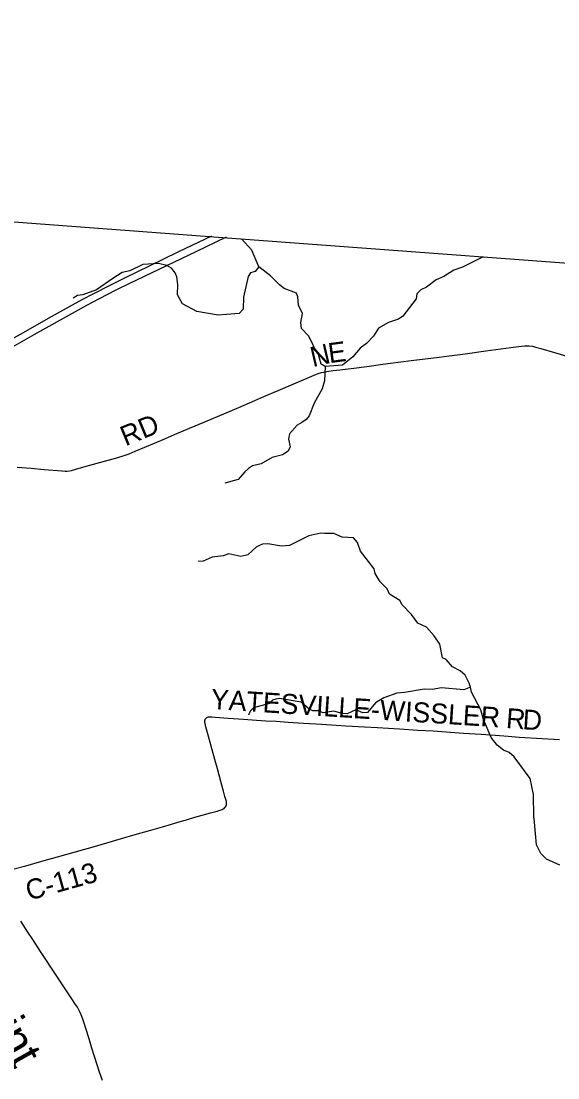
# Model space of a CAD drawing. Extents: x -51392 to 1635000, y 156707 to 696232.
# Drawn here: x 136510 to 144570, y 535301 to 551154 of the extents above; entities that cross this region are included whole.
import ezdxf

# ---------------------------------------------------------------- set-up
doc = ezdxf.new("R2010")
doc.units = 0
for name, color, linetype in [('GM_X_Adjacent_County', 7, 'Continuous'), ('GM_X_County', 7, 'Continuous'), ('GM_X_County_Road', 7, 'Continuous'), ('GM_X_County_Road_Text', 7, 'Continuous'), ('GM_X_Interstate_Route', 7, 'Continuous'), ('GM_X_Minor_River', 7, 'Continuous'), ('GM_X_Minor_River_Text', 7, 'Continuous'), ('GM_X_State_Route', 7, 'Continuous'), ('GM_X_Township', 7, 'Continuous'), ('GM_X_Township_Road', 7, 'Continuous'), ('GM_X_Township_Road_Text', 7, 'Continuous')]:
    doc.layers.add(name, color=color, linetype=linetype)

msp = doc.modelspace()

# ---------------------------------------------------------------- linework, layer by layer
at = {"layer": 'GM_X_Adjacent_County'}
msp.add_lwpolyline([(96623, 551154), (109974, 550151), (113344, 549888), (113818, 549851), (117011, 549602), (121021, 549289), (121855, 549224), (127787, 548783), (132864, 548406), (139538, 547909), (147829, 547293), (153416, 546885), (154887, 546778), (157022, 546663), (159649, 546538), (163080, 546381), (166694, 546239), (167692, 546175), (177006, 545575)], dxfattribs=at)
at = {"layer": 'GM_X_County'}
msp.add_lwpolyline([(96623, 551154), (109974, 550151), (113344, 549888), (113818, 549851), (117011, 549602), (121021, 549289), (121855, 549224), (127787, 548783), (132864, 548406), (139538, 547909), (147829, 547293), (153416, 546885), (154887, 546778), (157022, 546663), (159649, 546538), (163080, 546381), (166694, 546239), (167692, 546175), (177006, 545575)], dxfattribs=at)
at = {"layer": 'GM_X_County_Road'}
msp.add_lwpolyline([(136386, 538430), (136583, 538483), (136819, 538550), (137056, 538617), (137184, 538653), (137309, 538687), (137466, 538731), (137577, 538762), (138018, 538890), (138223, 538950), (138459, 539019), (138632, 539068), (138768, 539108), (138900, 539146), (138994, 539174), (139119, 539212), (139230, 539243), (139353, 539276), (139452, 539303), (139499, 539316), (139530, 539328), (139544, 539335), (139558, 539344), (139571, 539355), (139581, 539367), (139589, 539381), (139593, 539396), (139596, 539412), (139595, 539429), (139593, 539445), (139586, 539477), (139570, 539524), (139548, 539603), (139540, 539635), (139509, 539746), (139457, 539935), (139419, 540078), (139380, 540220), (139320, 540442), (139284, 540568), (139272, 540616), (139269, 540633), (139268, 540649), (139270, 540665), (139272, 540673), (139276, 540682), (139283, 540693), (139288, 540699), (139297, 540705), (139309, 540710), (139326, 540715), (139342, 540717), (139375, 540716), (139424, 540712), (139621, 540697), (139850, 540682), (140046, 540668), (140185, 540659), (140340, 540650), (140520, 540638), (140749, 540624), (141028, 540605), (141240, 540592), (141388, 540584), (141666, 540569), (141862, 540558), (142190, 540537), (142468, 540519), (142697, 540505), (142893, 540493), (143155, 540474), (143416, 540455), (143629, 540440), (143825, 540425), (143989, 540413), (144332, 540392), (144594, 540377)], dxfattribs=at)
at = {"layer": 'GM_X_Interstate_Route'}
for points in [[(136250, 546320), (136580, 546504), (136922, 546697), (137238, 546874), (137427, 546976), (137602, 547068), (137847, 547194), (138068, 547303), (138643, 547581), (138880, 547696), (139373, 547934)], [(136707, 546451), (137326, 546800), (137498, 546895), (137687, 546994), (137936, 547121), (138142, 547222), (139138, 547699), (139592, 547918)], [(134408, 545154), (134597, 545261), (135640, 545849), (135736, 545905), (136140, 546131), (136707, 546451)]]:
    msp.add_lwpolyline(points, dxfattribs=at)
at = {"layer": 'GM_X_Minor_River'}
for points in [[(143446, 547620), (143138, 547462), (143009, 547417), (142858, 547322), (142742, 547273), (142598, 547161), (142514, 547124), (142453, 547062), (142441, 546990), (142244, 546729), (142176, 546685), (142027, 546634), (141878, 546549), (141803, 546426), (141696, 546320), (141599, 546247), (141491, 546117), (141336, 545992), (141075, 545972), (141015, 546010), (140964, 546187), (140917, 546246), (140883, 546326), (140828, 546435), (140718, 546544), (140711, 546634), (140734, 546766), (140675, 546895), (140666, 547017), (140644, 547071), (140458, 547143), (140388, 547200), (140253, 547333), (140081, 547468), (139977, 547720), (139822, 547889)], [(140081, 547468), (140025, 547399), (139956, 547377), (139918, 547323), (139851, 547011), (139844, 546831), (139783, 546769), (139593, 546754), (139470, 546743), (139150, 546798), (138934, 546914), (138861, 547046), (138864, 547201), (138847, 547319), (138825, 547377), (138767, 547450), (138698, 547490), (138575, 547517), (138339, 547503), (138143, 547410), (138029, 547383), (137888, 547292), (137640, 547125), (137435, 547047), (137356, 547037), (137290, 547000)], [(141075, 545972), (141068, 545756), (141029, 545640), (140913, 545422), (140835, 545232), (140791, 545176), (140726, 545131), (140656, 545091), (140542, 544964), (140524, 544882), (140551, 544767), (140522, 544701), (140436, 544650), (140279, 544607), (140114, 544512), (139983, 544485), (139925, 544443), (139868, 544391), (139771, 544278), (139568, 544225)], [(142599, 542060), (142469, 542123), (142374, 542250), (142234, 542396), (142195, 542462), (142043, 542555), (142005, 542636), (141904, 542741), (141874, 542793), (141826, 542866), (141813, 542938), (141608, 543200), (141559, 543331), (141500, 543403), (141329, 543413), (141207, 543468), (141065, 543469), (141009, 543471), (140830, 543430), (140540, 543288), (140421, 543275), (140217, 543314), (140137, 543307), (140046, 543268), (139980, 543206), (139917, 543146), (139811, 543121), (139630, 543162), (139542, 543131), (139381, 543114), (139246, 543053), (139170, 543049)], [(144598, 538490), (144400, 538583), (144313, 538668), (144251, 538799), (144220, 539136), (144210, 539220), (144203, 539551), (144155, 539792), (143912, 540116), (143838, 540181), (143756, 540216), (143657, 540293), (143569, 540408), (143453, 540679), (143414, 540822), (143272, 541089), (143256, 541164), (143240, 541224), (143177, 541342), (143105, 541409), (142986, 541466), (142894, 541577), (142840, 541602), (142797, 541806), (142714, 541931), (142599, 542060)], [(143256, 541164), (143157, 541122), (142823, 541153), (142684, 541128), (142560, 541130), (142267, 541081), (142152, 541071), (141959, 541001), (141832, 540925), (141711, 540780), (141643, 540778), (141535, 540821), (141406, 540764), (141330, 540765), (141206, 540804), (141045, 540779), (140973, 540807), (140893, 540806), (140837, 540832), (140713, 540935), (140391, 540992), (140336, 540984), (140286, 540969), (140240, 540915), (140002, 540854), (139948, 540801), (139927, 540741)]]:
    msp.add_lwpolyline(points, dxfattribs=at)
at = {"layer": 'GM_X_State_Route'}
msp.add_lwpolyline([(137732, 535262), (137689, 535386), (137614, 535620), (137569, 535761), (137525, 535902), (137487, 536028), (137459, 536120), (137438, 536183), (137413, 536246), (137386, 536303), (137355, 536361), (137318, 536418), (137270, 536486), (137171, 536637), (137036, 536842), (136801, 537199), (136684, 537377), (136613, 537487), (136507, 537653)], dxfattribs=at)
at = {"layer": 'GM_X_Township'}
msp.add_lwpolyline([(121855, 549224), (127787, 548783), (132864, 548406), (139538, 547909), (147829, 547293)], dxfattribs=at)
at = {"layer": 'GM_X_Township_Road'}
msp.add_lwpolyline([(136451, 544465), (136663, 544447), (136859, 544429), (137121, 544407), (137170, 544404), (137203, 544404), (137235, 544408), (137267, 544414), (137331, 544431), (137488, 544476), (137709, 544539), (137946, 544605), (138056, 544638), (138133, 544665), (138225, 544702), (138512, 544823), (138678, 544892), (138813, 544951), (139040, 545047), (139267, 545143), (139780, 545360), (140021, 545463), (140157, 545521), (140368, 545611), (140639, 545727), (140911, 545843), (140972, 545867), (141019, 545883), (141050, 545890), (141099, 545899), (141196, 545911), (141294, 545923), (141505, 545950), (141701, 545975), (141944, 546008), (142058, 546023), (142366, 546063), (142790, 546114), (142936, 546133), (143180, 546165), (143489, 546207), (143862, 546256), (144025, 546278), (144074, 546282), (144107, 546283), (144140, 546282), (144188, 546276), (144236, 546265), (144315, 546243), (144519, 546182), (144740, 546117)], dxfattribs=at)

# ---------------------------------------------------------------- texts
at = {"layer": 'GM_X_County_Road_Text'}
for s, rotation, p in [('YATESVILLE-WISSLER', 356.3396, (139353, 540836)), ('R', 355.5639, (143784, 540551)), ('D', 356.4447, (144034, 540531)), ('C-113', 15.6334, (136627, 537958))]:
    msp.add_text(s, height=300, rotation=rotation, dxfattribs=at).set_placement(p)
at = {"layer": 'GM_X_Minor_River_Text'}
msp.add_text('Paint', height=500, rotation=299.3892, dxfattribs=at).set_placement((135666, 536753))
at = {"layer": 'GM_X_Township_Road_Text'}
for s, rotation, p in [('N', 13.2353, (140891, 545963)), ('E', 7.5503, (141140, 546022)), ('RD', 22.511, (138078, 544773))]:
    msp.add_text(s, height=300, rotation=rotation, dxfattribs=at).set_placement(p)

doc.saveas('drawing.dxf')
